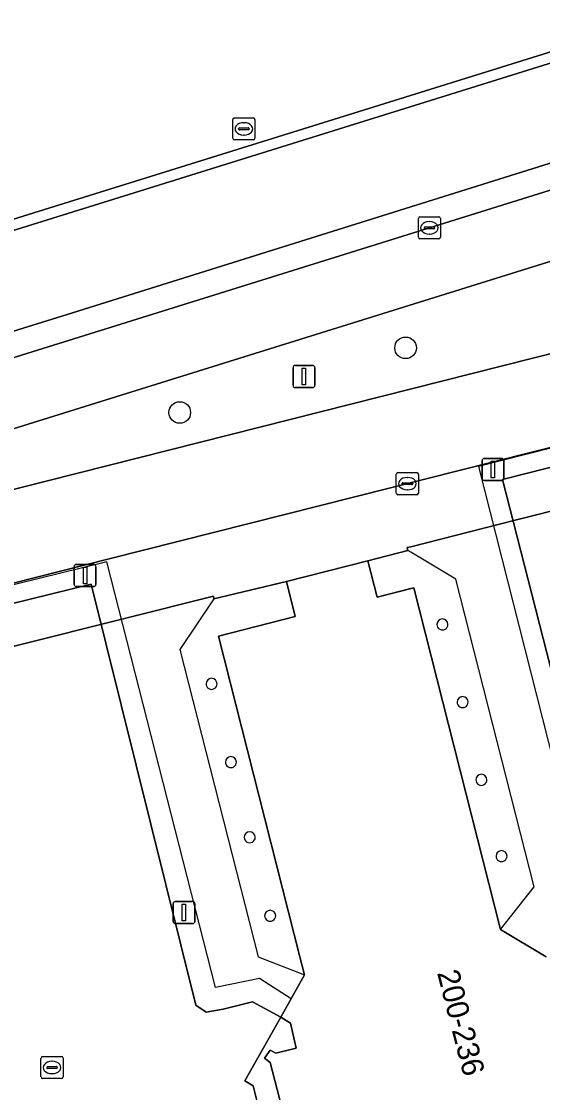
# Model space of a CAD drawing. Extents: x 160806 to 161707, y 383696 to 384148.
# Drawn here: x 160982.34 to 161005.97, y 383743.85 to 383792.38 of the extents above; entities that cross this region are included whole.
import ezdxf

# ---------------------------------------------------------------- set-up
doc = ezdxf.new("R2010")
doc.units = 0
for name, color, linetype in [('IMGEO_Berm_groen', 7, 'Continuous'), ('IMGEO_Boom', 7, 'Continuous'), ('IMGEO_Dek', 7, 'Continuous'), ('IMGEO_Fietspad_open', 7, 'Continuous'), ('IMGEO_Groenvoorziening', 7, 'Continuous'), ('IMGEO_Kolk', 7, 'Continuous'), ('IMGEO_Lichtmast', 7, 'Continuous'), ('IMGEO_Muur', 7, 'Continuous'), ('IMGEO_Pand', 7, 'Continuous'), ('IMGEO_Pand_nummerreeks', 7, 'Continuous'), ('IMGEO_Pand_overbouw', 7, 'Continuous'), ('IMGEO_Parkeervlak_gesloten', 7, 'Continuous'), ('IMGEO_Parkeervlak_open', 7, 'Continuous'), ('IMGEO_Rioolput', 7, 'Continuous'), ('IMGEO_Voetpad_gesloten', 7, 'Continuous'), ('IMGEO_Voetpad_open', 7, 'Continuous')]:
    doc.layers.add(name, color=color, linetype=linetype)

msp = doc.modelspace()

# ---------------------------------------------------------------- linework, layer by layer
at = {"layer": 'IMGEO_Berm_groen'}
msp.add_lwpolyline([(161019.729, 383788.913), (161049.506, 383798.192), (161050.285, 383798.436), (161049.357, 383799.265), (161036.436, 383795.305), (161012.779, 383787.972), (161000, 383783.977), (160984.412, 383779.104), (160968.351, 383774.113), (160967.332, 383773.795), (160957.725, 383770.797), (160956.274, 383770.344), (160948.254, 383767.825), (160948.598, 383766.747), (160956.559, 383769.228), (160958.007, 383769.679), (160967.617, 383772.674), (160968.627, 383772.989)], close=True, dxfattribs=at)
msp.add_lwpolyline([(161040.229, 383792.065), (161020.639, 383785.965), (160969.362, 383769.998), (160968.372, 383769.69), (160966.401, 383769.076), (160966.901, 383767.371), (160968.836, 383767.86), (160969.826, 383768.11), (161021.959, 383781.273)], dxfattribs=at)
at = {"layer": 'IMGEO_Boom'}
for centre in [(160999.756, 383777.588), (160989.52, 383774.659)]:
    msp.add_circle(centre, 0.489, dxfattribs=at)
at = {"layer": 'IMGEO_Dek'}
for points in [[(161034.181, 383780.096), (161003.066, 383772.21), (161015.684, 383722.436)], [(160994.485, 383741.89), (160993.613, 383745.213), (160993.358, 383745.414), (160993.622, 383745.772), (160993.877, 383745.634), (160994.802, 383745.868), (160994.541, 383746.997), (160994.095, 383747.26), (160994.57, 383748.102), (160993.134, 383749.019), (160991.136, 383748.615), (160986.209, 383767.888), (160970.809, 383764.107), (160969.826, 383768.11), (160969.362, 383769.998), (160968.627, 383772.989), (160968.588, 383773.147), (160968.351, 383774.113), (160967.312, 383778.34), (160966.993, 383778.241), (160966.874, 383778.714), (160966.145, 383778.487), (160956.543, 383775.501), (160955.438, 383775.157)]]:
    msp.add_lwpolyline(points, dxfattribs=at)
at = {"layer": 'IMGEO_Fietspad_open'}
for points in [[(161052.515, 383788.49), (161049.506, 383798.192), (161019.729, 383788.913), (160968.627, 383772.989), (160967.617, 383772.674), (160958.007, 383769.679), (160956.559, 383769.228), (160948.598, 383766.747), (160944.425, 383765.465)], [(160945.348, 383762.558), (160957.316, 383766.263), (160958.754, 383766.709), (160966.401, 383769.076), (160968.372, 383769.69), (160969.362, 383769.998), (161020.639, 383785.965), (161040.229, 383792.065)], [(161041.412, 383786.184), (161021.959, 383781.273), (160969.826, 383768.11), (160968.836, 383767.86), (160966.901, 383767.371), (160959.078, 383765.421), (160957.624, 383765.058), (160945.5, 383762.036)], [(160947.606, 383758.324), (160957.999, 383760.873), (160958.651, 383761.038), (160960.089, 383761.401), (160969.85, 383763.865), (160970.809, 383764.107), (160986.327, 383768.025), (161022.896, 383777.258), (161039.914, 383781.555), (161040.772, 383781.738)]]:
    msp.add_lwpolyline(points, dxfattribs=at)
at = {"layer": 'IMGEO_Groenvoorziening'}
for points in [[(160966.183, 383791.701), (160969.268, 383779.462), (161039.411, 383801.315), (161041.733, 383801.767)], [(161041.832, 383801.291), (161039.53, 383800.843), (160967.312, 383778.34), (160966.993, 383778.241), (160966.263, 383778.014), (160956.661, 383775.029), (160955.538, 383774.68), (160955.193, 383774.577), (160946.889, 383772.105), (160948.254, 383767.825), (160956.274, 383770.344), (160957.725, 383770.797), (160967.332, 383773.795), (160968.351, 383774.113), (160984.412, 383779.104), (161000, 383783.977), (161012.779, 383787.972)]]:
    msp.add_lwpolyline(points, dxfattribs=at)
at = {"layer": 'IMGEO_Kolk'}
for p, q in [((161000.334, 383782.599), (161000.334, 383783.451)), ((161000.409, 383783.525), (161001.261, 383783.525)), ((161000.822, 383783.305), (161000.847, 383783.305)), ((161001.335, 383783.451), (161001.335, 383782.599)), ((161000.593, 383783.019), (161000.593, 383783.031)), ((161001.031, 383782.982), (161000.633, 383782.982)), ((161000.636, 383783.068), (161001.034, 383783.068)), ((161001.077, 383783.031), (161001.077, 383783.019)), ((161001.261, 383782.525), (161000.409, 383782.525)), ((161000.845, 383782.745), (161000.82, 383782.745)), ((160999.336, 383771.01), (160999.336, 383771.862)), ((160999.411, 383771.936), (161000.263, 383771.936)), ((160999.824, 383771.716), (160999.849, 383771.716)), ((161000.337, 383771.862), (161000.337, 383771.01)), ((160999.595, 383771.43), (160999.595, 383771.442)), ((161000.033, 383771.393), (160999.635, 383771.393)), ((160999.638, 383771.479), (161000.036, 383771.479)), ((160999.847, 383771.156), (160999.822, 383771.156)), ((161000.079, 383771.442), (161000.079, 383771.43)), ((161000.263, 383770.936), (160999.411, 383770.936))]:
    msp.add_line(p, q, dxfattribs=at)
for points in [[(161000.334, 383782.599), (161000.334, 383783.451)], [(161000.409, 383783.525), (161001.261, 383783.525)], [(161001.335, 383783.451), (161001.335, 383782.599)], [(161001.261, 383782.525), (161000.409, 383782.525)], [(160999.336, 383771.01), (160999.336, 383771.862)], [(160999.411, 383771.936), (161000.263, 383771.936)], [(161000.337, 383771.862), (161000.337, 383771.01)], [(161000.263, 383770.936), (160999.411, 383770.936)]]:
    msp.add_lwpolyline(points, dxfattribs=at)
for centre, radius, start, end in [((161000.411, 383783.449), 0.0765, 91.552, 178.448), ((161000.411, 383783.449), 0.0765, 91.552, 178.448), ((161001.259, 383783.449), 0.0765, 1.552, 88.448), ((161001.259, 383783.449), 0.0765, 1.552, 88.448), ((161000.633, 383783.028), 0.0403, 85.8775, 175.7526), ((161000.63, 383783.018), 0.0366, 178.938, 274.7102), ((161001.034, 383783.025), 0.043, 264.8664, 352.4533), ((161001.038, 383783.03), 0.0386, 1.7309, 96.639), ((161000.411, 383782.601), 0.0765, 181.552, 268.448), ((161000.411, 383782.601), 0.0765, 181.552, 268.448), ((161001.259, 383782.601), 0.0765, 271.552, 358.448), ((161001.259, 383782.601), 0.0765, 271.552, 358.448), ((160999.413, 383771.86), 0.0765, 91.552, 178.448), ((160999.413, 383771.86), 0.0765, 91.552, 178.448), ((161000.261, 383771.86), 0.0765, 1.552, 88.448), ((161000.261, 383771.86), 0.0765, 1.552, 88.448), ((160999.635, 383771.439), 0.0403, 85.8775, 175.7526), ((160999.632, 383771.429), 0.0366, 178.938, 274.7102), ((161000.036, 383771.436), 0.043, 264.8664, 352.4533), ((161000.04, 383771.441), 0.0386, 1.7309, 96.639), ((160999.413, 383771.012), 0.0765, 181.552, 268.448), ((160999.413, 383771.012), 0.0765, 181.552, 268.448), ((161000.261, 383771.012), 0.0765, 271.552, 358.448), ((161000.261, 383771.012), 0.0765, 271.552, 358.448)]:
    msp.add_arc(centre, radius, start, end, dxfattribs=at)
for centre, major_axis, ratio, start_param, end_param in [((161000.821, 383783.025), (-0.387, 0.002), 0.722429, 4.712389, 7.853982), ((161000.846, 383783.025), (-0.39, 0.002), 0.717154, 1.570796, 4.712389), ((160999.823, 383771.436), (-0.387, 0.002), 0.722429, 4.712389, 7.853982), ((160999.848, 383771.436), (-0.39, 0.002), 0.717154, 1.570796, 4.712389)]:
    msp.add_ellipse(centre, major_axis=major_axis, ratio=ratio, start_param=start_param, end_param=end_param, dxfattribs=at)
at = {"layer": 'IMGEO_Lichtmast'}
for p, q in [((160994.653, 383775.89), (160994.653, 383776.69)), ((160994.653, 383776.69), (160994.653, 383775.89)), ((160994.753, 383776.79), (160995.543, 383776.79)), ((160995.543, 383776.79), (160994.753, 383776.79)), ((160995.643, 383776.69), (160995.643, 383775.89)), ((160995.643, 383775.89), (160995.643, 383776.69)), ((160995.543, 383775.79), (160994.753, 383775.79)), ((160994.753, 383775.79), (160995.543, 383775.79)), ((161003.222, 383771.681), (161003.222, 383772.481)), ((161003.222, 383772.481), (161003.222, 383771.681)), ((161003.322, 383772.581), (161004.112, 383772.581)), ((161004.112, 383772.581), (161003.322, 383772.581)), ((161004.212, 383772.481), (161004.212, 383771.681)), ((161004.212, 383771.681), (161004.212, 383772.481)), ((161004.112, 383771.581), (161003.322, 383771.581)), ((161003.322, 383771.581), (161004.112, 383771.581)), ((160984.832, 383767.773), (160985.622, 383767.773)), ((160985.622, 383767.773), (160984.832, 383767.773)), ((160984.732, 383766.873), (160984.732, 383767.673)), ((160984.732, 383767.673), (160984.732, 383766.873)), ((160985.722, 383767.673), (160985.722, 383766.873)), ((160985.722, 383766.873), (160985.722, 383767.673)), ((160985.622, 383766.773), (160984.832, 383766.773)), ((160984.832, 383766.773), (160985.622, 383766.773)), ((160989.215, 383751.603), (160989.215, 383752.403)), ((160989.215, 383752.403), (160989.215, 383751.603)), ((160989.315, 383752.503), (160990.105, 383752.503)), ((160990.105, 383752.503), (160989.315, 383752.503)), ((160990.205, 383752.403), (160990.205, 383751.603)), ((160990.205, 383751.603), (160990.205, 383752.403)), ((160990.105, 383751.503), (160989.315, 383751.503)), ((160989.315, 383751.503), (160990.105, 383751.503))]:
    msp.add_line(p, q, dxfattribs=at)
for points in [[(160995.073, 383776.665), (160995.223, 383776.665), (160995.223, 383775.915), (160995.073, 383775.915), (160995.073, 383776.665)], [(161003.642, 383772.456), (161003.792, 383772.456), (161003.792, 383771.706), (161003.642, 383771.706), (161003.642, 383772.456)], [(160985.152, 383767.648), (160985.302, 383767.648), (160985.302, 383766.898), (160985.152, 383766.898), (160985.152, 383767.648)], [(160989.635, 383752.378), (160989.785, 383752.378), (160989.785, 383751.628), (160989.635, 383751.628), (160989.635, 383752.378)]]:
    msp.add_lwpolyline(points, dxfattribs=at)
for centre, start, end in [((160994.753, 383776.69), 90, 180), ((160994.753, 383776.69), 90, 180), ((160995.543, 383776.69), 0, 90), ((160995.543, 383776.69), 360, 90), ((160994.753, 383775.89), 180, 270), ((160994.753, 383775.89), 180, 270), ((160995.543, 383775.89), 270, 0), ((160995.543, 383775.89), 270, 0), ((161003.322, 383772.481), 90, 180), ((161003.322, 383772.481), 90, 180), ((161004.112, 383772.481), 0, 90), ((161004.112, 383772.481), 360, 90), ((161003.322, 383771.681), 180, 270), ((161003.322, 383771.681), 180, 270), ((161004.112, 383771.681), 270, 0), ((161004.112, 383771.681), 270, 0), ((160984.832, 383767.673), 90, 180), ((160984.832, 383767.673), 90, 180), ((160985.622, 383767.673), 0, 90), ((160985.622, 383767.673), 360, 90), ((160984.832, 383766.873), 180, 270), ((160984.832, 383766.873), 180, 270), ((160985.622, 383766.873), 270, 0), ((160985.622, 383766.873), 270, 0), ((160989.315, 383752.403), 90, 180), ((160989.315, 383752.403), 90, 180), ((160990.105, 383752.403), 0, 90), ((160990.105, 383752.403), 360, 90), ((160989.315, 383751.603), 180, 270), ((160989.315, 383751.603), 180, 270), ((160990.105, 383751.603), 270, 0), ((160990.105, 383751.603), 270, 0)]:
    msp.add_arc(centre, 0.1, start, end, dxfattribs=at)
at = {"layer": 'IMGEO_Muur'}
for points in [[(161041.733, 383801.767), (161039.411, 383801.315), (160969.268, 383779.462), (160966.874, 383778.714), (160966.145, 383778.487), (160956.543, 383775.501), (160955.438, 383775.157), (160953.439, 383774.547), (160944.875, 383771.933), (160942.421, 383771.184)], [(160942.522, 383770.805), (160946.889, 383772.105), (160955.193, 383774.577), (160955.538, 383774.68), (160956.661, 383775.029), (160966.263, 383778.014), (160966.993, 383778.241), (160967.312, 383778.34), (161039.53, 383800.843)]]:
    msp.add_lwpolyline(points, dxfattribs=at)
at = {"layer": 'IMGEO_Pand'}
msp.add_lwpolyline([(161006.133, 383750), (161004.057, 383751.235), (161000.122, 383766.719), (161000, 383766.688), (160998.461, 383766.297), (160998.042, 383767.944), (160994.355, 383767.007), (160994.758, 383765.418), (160991.276, 383764.533), (160994.969, 383750), (160995.178, 383749.179), (160994.527, 383748.026), (160994.095, 383747.26), (160994.541, 383746.997), (160994.802, 383745.868), (160993.877, 383745.634), (160993.622, 383745.772), (160993.358, 383745.414), (160993.613, 383745.213), (160994.485, 383741.89)], dxfattribs=at)
for centre, start, end in [((161001.426, 383765.056), 0.2296, 179.7704), ((161001.426, 383765.056), 179.7713, 0.2287), ((160990.962, 383762.366), 0.2296, 179.7704), ((160990.962, 383762.366), 179.7713, 0.2287), ((161002.34, 383761.537), 0.2296, 179.7704), ((161002.34, 383761.537), 179.7713, 0.2287), ((160991.839, 383758.821), 0.2296, 179.7704), ((160991.839, 383758.821), 179.7713, 0.2287), ((161003.19, 383758.017), 0.2296, 179.7704), ((161003.19, 383758.017), 179.7713, 0.2287), ((160992.691, 383755.416), 0.2296, 179.7704), ((160992.691, 383755.416), 179.7713, 0.2287), ((161004.104, 383754.561), 0.2296, 179.7704), ((161004.104, 383754.561), 179.7713, 0.2287), ((160993.618, 383751.859), 0.2296, 179.7704), ((160993.618, 383751.859), 179.7713, 0.2287)]:
    msp.add_arc(centre, 0.25, start, end, dxfattribs=at)
at = {"layer": 'IMGEO_Pand_overbouw'}
for points in [[(161002.04, 383767.101), (161000, 383768.326), (160999.864, 383768.408), (160998.042, 383767.944), (160998.461, 383766.297), (161000.122, 383766.719), (161004.057, 383751.235), (161005.58, 383753.168)], [(160989.531, 383763.922), (160993.071, 383750), (160995.178, 383749.179), (160994.969, 383750), (160991.276, 383764.533), (160994.758, 383765.418), (160994.355, 383767.007), (160991.065, 383766.218)], [(160994.095, 383747.26), (160992.471, 383744.38), (160992.846, 383744.157), (160993.322, 383742.286), (160993.135, 383742.01), (160995.873, 383740.381), (160996.079, 383740.719), (160995.793, 383741.886), (160994.804, 383741.626), (160994.615, 383741.383), (160994.347, 383741.673), (160994.485, 383741.89), (160993.613, 383745.213), (160993.358, 383745.414), (160993.622, 383745.772), (160993.877, 383745.634), (160994.802, 383745.868), (160994.541, 383746.997)]]:
    msp.add_lwpolyline(points, close=True, dxfattribs=at)
at = {"layer": 'IMGEO_Parkeervlak_gesloten'}
for points in [[(161033.086, 383778.968), (161004.152, 383771.617), (161016.514, 383723.323)], [(160993.322, 383742.286), (160992.846, 383744.157), (160992.471, 383744.38), (160994.095, 383747.26), (160992.821, 383747.959), (160991.495, 383747.627), (160990.71, 383747.495), (160990.251, 383747.813), (160985.51, 383766.882), (160971.605, 383763.473), (160974.981, 383749.905), (160975.93, 383750.029), (160976.135, 383749.107), (160974.285, 383748.798), (160975.479, 383744.309), (160976.667, 383739.892)]]:
    msp.add_lwpolyline(points, dxfattribs=at)
at = {"layer": 'IMGEO_Parkeervlak_open'}
for points in [[(161033.628, 383777.039), (161004.728, 383769.776), (161004.015, 383769.597), (161000, 383768.578), (160999.833, 383768.536), (160999.864, 383768.408), (160998.042, 383767.944), (160998.461, 383766.297), (161000, 383766.688), (161000.122, 383766.719), (161004.057, 383751.235), (161006.133, 383750)], [(160994.485, 383741.89), (160993.613, 383745.213), (160993.358, 383745.414), (160993.622, 383745.772), (160993.877, 383745.634), (160994.802, 383745.868), (160994.541, 383746.997), (160994.095, 383747.26), (160994.527, 383748.026), (160995.178, 383749.179), (160994.969, 383750), (160991.276, 383764.533), (160994.758, 383765.418), (160994.355, 383767.007), (160991.065, 383766.218), (160991.046, 383766.335), (160987.014, 383765.325), (160985.922, 383765.051), (160972.153, 383761.59), (160971.208, 383761.353), (160960.762, 383758.727), (160959.333, 383758.368), (160959.395, 383758.125), (160946.757, 383754.904)]]:
    msp.add_lwpolyline(points, dxfattribs=at)
for centre, start, end in [((161001.426, 383765.056), 0.2296, 179.7704), ((161001.426, 383765.056), 179.7713, 0.2287), ((160990.962, 383762.366), 0.2296, 179.7704), ((160990.962, 383762.366), 179.7713, 0.2287), ((161002.34, 383761.537), 0.2296, 179.7704), ((161002.34, 383761.537), 179.7713, 0.2287), ((160991.839, 383758.821), 0.2296, 179.7704), ((160991.839, 383758.821), 179.7713, 0.2287), ((161003.19, 383758.017), 0.2296, 179.7704), ((161003.19, 383758.017), 179.7713, 0.2287), ((160992.691, 383755.416), 0.2296, 179.7704), ((160992.691, 383755.416), 179.7713, 0.2287), ((161004.104, 383754.561), 0.2296, 179.7704), ((161004.104, 383754.561), 179.7713, 0.2287), ((160993.618, 383751.859), 0.2296, 179.7704), ((160993.618, 383751.859), 179.7713, 0.2287)]:
    msp.add_arc(centre, 0.25, start, end, dxfattribs=at)
at = {"layer": 'IMGEO_Rioolput'}
for p, q in [((160991.925, 383787.081), (160991.925, 383787.933)), ((160992, 383788.007), (160992.852, 383788.007)), ((160992.413, 383787.787), (160992.438, 383787.787)), ((160992.926, 383787.933), (160992.926, 383787.081)), ((160992.184, 383787.501), (160992.184, 383787.513)), ((160992.622, 383787.464), (160992.224, 383787.464)), ((160992.227, 383787.55), (160992.625, 383787.55)), ((160992.436, 383787.227), (160992.411, 383787.227)), ((160992.668, 383787.513), (160992.668, 383787.501)), ((160992.852, 383787.007), (160992, 383787.007)), ((160983.306, 383745.485), (160984.158, 383745.485)), ((160983.231, 383744.559), (160983.231, 383745.411)), ((160983.49, 383744.979), (160983.49, 383744.991)), ((160983.928, 383744.942), (160983.53, 383744.942)), ((160983.533, 383745.028), (160983.931, 383745.028)), ((160983.719, 383745.265), (160983.744, 383745.265)), ((160983.974, 383744.991), (160983.974, 383744.979)), ((160984.232, 383745.411), (160984.232, 383744.559)), ((160984.158, 383744.485), (160983.306, 383744.485)), ((160983.742, 383744.705), (160983.717, 383744.705))]:
    msp.add_line(p, q, dxfattribs=at)
for points in [[(160991.925, 383787.081), (160991.925, 383787.933)], [(160992, 383788.007), (160992.852, 383788.007)], [(160992.926, 383787.933), (160992.926, 383787.081)], [(160992.852, 383787.007), (160992, 383787.007)], [(160983.306, 383745.485), (160984.158, 383745.485)], [(160983.231, 383744.559), (160983.231, 383745.411)], [(160984.232, 383745.411), (160984.232, 383744.559)], [(160984.158, 383744.485), (160983.306, 383744.485)]]:
    msp.add_lwpolyline(points, dxfattribs=at)
for centre, radius, start, end in [((160992.002, 383787.931), 0.0765, 91.552, 178.448), ((160992.002, 383787.931), 0.0765, 91.552, 178.448), ((160992.85, 383787.931), 0.0765, 1.552, 88.448), ((160992.85, 383787.931), 0.0765, 1.552, 88.448), ((160992.224, 383787.51), 0.0403, 85.8775, 175.7526), ((160992.221, 383787.5), 0.0366, 178.938, 274.7102), ((160992.625, 383787.507), 0.043, 264.8664, 352.4533), ((160992.629, 383787.512), 0.0386, 1.7309, 96.639), ((160992.002, 383787.083), 0.0765, 181.552, 268.448), ((160992.002, 383787.083), 0.0765, 181.552, 268.448), ((160992.85, 383787.083), 0.0765, 271.552, 358.448), ((160992.85, 383787.083), 0.0765, 271.552, 358.448), ((160983.308, 383745.409), 0.0765, 91.552, 178.448), ((160983.308, 383745.409), 0.0765, 91.552, 178.448), ((160984.156, 383745.409), 0.0765, 1.552, 88.448), ((160984.156, 383745.409), 0.0765, 1.552, 88.448), ((160983.53, 383744.988), 0.0403, 85.8775, 175.7526), ((160983.527, 383744.978), 0.0366, 178.938, 274.7102), ((160983.931, 383744.985), 0.043, 264.8664, 352.4533), ((160983.935, 383744.99), 0.0386, 1.7309, 96.639), ((160983.308, 383744.561), 0.0765, 181.552, 268.448), ((160983.308, 383744.561), 0.0765, 181.552, 268.448), ((160984.156, 383744.561), 0.0765, 271.552, 358.448), ((160984.156, 383744.561), 0.0765, 271.552, 358.448)]:
    msp.add_arc(centre, radius, start, end, dxfattribs=at)
for centre, major_axis, ratio, start_param, end_param in [((160992.412, 383787.507), (-0.387, 0.002), 0.722429, 4.712389, 7.853982), ((160992.437, 383787.507), (-0.39, 0.002), 0.717154, 1.570796, 4.712389), ((160983.718, 383744.985), (-0.387, 0.002), 0.722429, 4.712389, 7.853982), ((160983.743, 383744.985), (-0.39, 0.002), 0.717154, 1.570796, 4.712389)]:
    msp.add_ellipse(centre, major_axis=major_axis, ratio=ratio, start_param=start_param, end_param=end_param, dxfattribs=at)
at = {"layer": 'IMGEO_Voetpad_gesloten'}
for points in [[(161047.689, 383726.041), (161047.527, 383726.542), (161047.162, 383727.994), (161034.181, 383780.096), (161003.066, 383772.21), (161015.684, 383722.436), (160997.975, 383721.941), (160993.948, 383737.691), (160995.883, 383738.073), (160996.869, 383739.789), (160995.99, 383740.312), (160995.138, 383738.871), (160993.141, 383738.5), (160992.783, 383737.964), (160996.841, 383721.416), (160997.147, 383721.192), (161020.567, 383722.095)], [(161020.163, 383724.26), (161016.514, 383723.323), (161004.152, 383771.617), (161033.086, 383778.968), (161046.335, 383726.393), (161041.226, 383717.794), (161017.446, 383716.817), (161017.462, 383716.268), (161017.47, 383715.97), (161042.245, 383716.936), (161047.689, 383726.041)]]:
    msp.add_lwpolyline(points, dxfattribs=at)
msp.add_lwpolyline([(160993.134, 383749.019), (160991.136, 383748.615), (160986.209, 383767.888), (160970.809, 383764.107), (160970.896, 383763.766), (160970.88, 383763.726), (160970.719, 383763.332), (160971.205, 383761.352), (160974.285, 383748.798), (160976.135, 383749.107), (160975.93, 383750.029), (160974.981, 383749.905), (160971.605, 383763.473), (160985.51, 383766.882), (160990.251, 383747.813), (160990.71, 383747.495), (160991.495, 383747.627), (160992.821, 383747.959), (160994.095, 383747.26), (160994.57, 383748.102)], close=True, dxfattribs=at)
at = {"layer": 'IMGEO_Voetpad_open'}
for points in [[(161040.772, 383781.738), (161039.914, 383781.555), (161022.896, 383777.258), (160986.327, 383768.025), (160970.809, 383764.107), (160969.85, 383763.865), (160960.089, 383761.401), (160958.651, 383761.038), (160957.999, 383760.873), (160947.606, 383758.324)], [(160971.208, 383761.353), (160972.153, 383761.59), (160985.922, 383765.051), (160987.014, 383765.325), (160991.046, 383766.335), (160991.065, 383766.218), (160994.355, 383767.007), (160998.042, 383767.944), (160999.864, 383768.408), (160999.833, 383768.536), (161000, 383768.578), (161004.015, 383769.597), (161004.728, 383769.776), (161033.628, 383777.039), (161034.135, 383777.166), (161034.767, 383777.324), (161035.404, 383777.485), (161040.404, 383778.741)]]:
    msp.add_lwpolyline(points, dxfattribs=at)

# ---------------------------------------------------------------- texts
at = {"layer": 'IMGEO_Pand_nummerreeks'}
msp.add_text('200-236', height=1, rotation=284.3868, dxfattribs=at).set_placement((161001.179, 383749.277))

doc.saveas('drawing.dxf')
